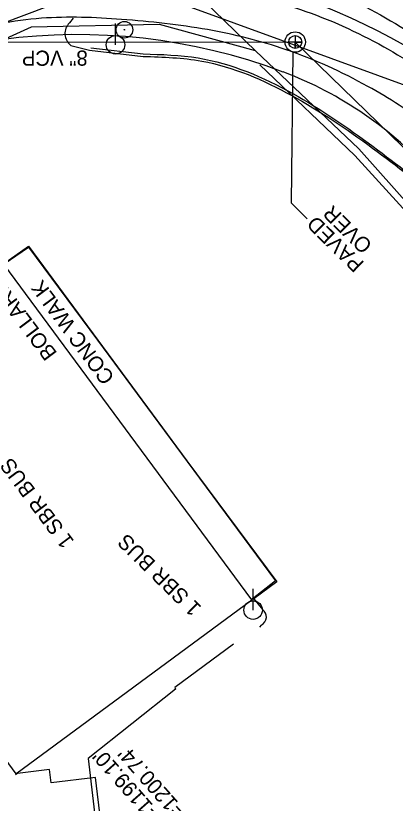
# Model space of a CAD drawing. Extents: x 1263837 to 1268319, y 770628 to 773628.
# Drawn here: x 1266313 to 1266413.1, y 772202.1 to 772410.1 of the extents above; entities that cross this region are included whole.
import ezdxf

# ---------------------------------------------------------------- set-up
doc = ezdxf.new("R2010")
doc.units = 0
for name, color, linetype in [('Exist Building', 7, 'Continuous'), ('Exist Building Text', 7, 'Continuous'), ('Exist Other Culture Located Object Text', 7, 'Continuous'), ('Exist Roads EOP Other', 7, 'Continuous'), ('Exist Roads EOP Other Text', 7, 'Continuous'), ('Exist Structure Minor Drop Inlet Top Elevation', 7, 'Continuous'), ('Exist Utilities Gas UG Line SUE LOS B', 7, 'Continuous'), ('Exist Utilities Gas UG Line SUE LOS C', 7, 'Continuous'), ('Exist Utilities Power Pole CELL', 7, 'Continuous'), ('Exist Utilities Water UG Line SUE LOS B', 7, 'Continuous'), ('Pattern 2', 7, 'Continuous'), ('Prop Conc 4in Sidewalk', 7, 'Continuous'), ('Prop Drainage Structure Junction Box Convert From Catch Basin Label', 7, 'Continuous'), ('Prop Horizontal Alignment', 7, 'Continuous'), ('Prop Retaining Wall', 7, 'Continuous'), ('Prop SS Fill Line', 7, 'Continuous'), ('Prop SS Fill Text', 7, 'Continuous'), ('Prop SS Transition Line', 7, 'Continuous'), ('Prop WCR CELL', 7, 'Continuous'), ('Scratch_Level_0', 7, 'Continuous'), ('Scratch_Level_2', 7, 'Continuous'), ('Scratch_Level_5', 7, 'Continuous')]:
    doc.layers.add(name, color=color, linetype=linetype)

# ---------------------------------------------------------------- blocks, each defined once
blk = doc.blocks.new('EXIST PROPERTY IRON PIN')
at = {"layer": 'Prop Conc 4in Sidewalk'}
for radius in [0.0441, 0.00141]:
    blk.add_circle((0, 0), radius, dxfattribs=at)
blk = doc.blocks.new('EXIST UTILITIES SANITARY SEWER MANHOLE')
at = {"layer": 'Prop WCR CELL'}
blk.add_lwpolyline([(0, 0.03425), (0, -0.03425), (0, 0), (0.03425, 0), (-0.03425, 0)], dxfattribs=at)
for radius in [0.05389, 0.03425]:
    blk.add_circle((0, 0), radius, dxfattribs=at)
blk = doc.blocks.new('EXIST UTILITIES POWER POLE')
at = {"layer": 'Exist Utilities Power Pole CELL'}
for q in [(0, 0.1125), (0, 0)]:
    blk.add_line((0, 0), q, dxfattribs=at)
blk.add_circle((0, 0), 0.049, dxfattribs=at)

msp = doc.modelspace()

# ---------------------------------------------------------------- linework, layer by layer
at = {"layer": 'Exist Building'}
for p, q in [((1266375.23, 772255.85), (1266309.82, 772344.48)), ((1266247.59, 772298.56), (1266312.99, 772209.92)), ((1266312.99, 772209.92), (1266375.23, 772255.85)), ((1266321.91, 772211.03), (1266313.4, 772209.99)), ((1266322.35, 772207.49), (1266321.91, 772211.03)), ((1266313.4, 772209.99), (1266312.91, 772209.63)), ((1266334.03, 772208.92), (1266322.35, 772207.49)), ((1266337.14, 772183.48), (1266334.03, 772208.92))]:
    msp.add_line(p, q, dxfattribs=at)
at = {"layer": 'Exist Roads EOP Other'}
msp.add_lwpolyline([(1266309.94, 772344.54), (1266316.31, 772348.99), (1266334.51, 772324.38), (1266358.19, 772292.37), (1266381.55, 772260.83), (1266375.33, 772256.01)], dxfattribs=at)
at = {"layer": 'Exist Utilities Gas UG Line SUE LOS B'}
for points in [[(1266634.89, 772116.41), (1266617.88, 772134.08), (1266593.74, 772162.87), (1266570.59, 772187.5), (1266552.2, 772208.93), (1266533.9, 772229.88), (1266520.79, 772243.67), (1266506.09, 772258.4), (1266476.3, 772293.88), (1266450.61, 772322.46), (1266432.17, 772342.72), (1266403.52, 772374.96), (1266376.24, 772400.79), (1266349.14, 772427.18), (1266329.27, 772447.31), (1266306.87, 772470.18), (1266286, 772492.58), (1266264.53, 772515.83), (1266241.63, 772542.64), (1266214.18, 772573.35), (1266190.07, 772598.41)], [(1266376.24, 772400.79), (1266350.86, 772407.74), (1266317.08, 772407.04), (1266271.2, 772386.3), (1266203.97, 772354.59), (1266162.66, 772329.58), (1266106.83, 772288), (1266086.58, 772274.45), (1266074.1, 772266.05)]]:
    msp.add_lwpolyline(points, dxfattribs=at)
at = {"layer": 'Exist Utilities Gas UG Line SUE LOS C'}
msp.add_lwpolyline([(1266457.07, 772059.93), (1266485, 772121.03), (1266506.31, 772156.87), (1266540.43, 772198.08), (1266541.09, 772218.23), (1266505.13, 772257.1), (1266475.32, 772292.21), (1266449.64, 772321.32), (1266402.45, 772373.22), (1266377.36, 772397.1)], dxfattribs=at)
at = {"layer": 'Exist Utilities Water UG Line SUE LOS B'}
msp.add_lwpolyline([(1266813.73, 772072.54), (1266793.78, 772088.05), (1266755.27, 772103.69), (1266718.33, 772109.44), (1266678.54, 772111.01), (1266653.19, 772143.96), (1266605.92, 772197.31), (1266538.03, 772271.69), (1266479.88, 772335.62), (1266421.78, 772389.51), (1266357.3, 772412.97), (1266321.15, 772412.43), (1266255.77, 772387.79), (1266212.97, 772357.83), (1266212.08, 772352.35), (1266208.85, 772350.26), (1266194.96, 772350.29), (1266178.01, 772373.6), (1266155.19, 772357.9), (1266088.3, 772309.2), (1266057.71, 772286.98)], dxfattribs=at)
at = {"layer": 'Pattern 2'}
msp.add_lwpolyline([(1266386.06, 772400.45), (1266385.61, 772360.68), (1266389.89, 772356.47)], dxfattribs=at)
at = {"layer": 'Prop Horizontal Alignment'}
for centre, radius, start, end in [((1275094.23, 780056.99), 11329.16, 216.983333, 223.309327), ((1266329.37, 772251.49), 153.62, 69.344, 125.8167), ((1266348.29, 772301.67), 100, 41.5645, 69.344)]:
    msp.add_arc(centre, radius, start, end, dxfattribs=at)
at = {"layer": 'Prop SS Fill Line'}
msp.add_line((1266332.8, 772401.59), (1266346.6, 772400.02), dxfattribs=at)
msp.add_spline([(1266346.6, 772400.02), (1266361.11, 772398.95), (1266386.07, 772389.55), (1266407.24, 772375.55), (1266426.22, 772361.02)], degree=3, dxfattribs=at)
at = {"layer": 'Prop SS Fill Text'}
for p, q in [((1266328.16, 772409.43), (1266327.13, 772408.22)), ((1266327.49, 772402.28), (1266332.41, 772401.03)), ((1266332.41, 772401.03), (1266346.62, 772399.36)), ((1266377.75, 772249.19), (1266377.27, 772248.65))]:
    msp.add_line(p, q, dxfattribs=at)
for points in [[(1266254.12, 772303.49), (1266281.48, 772323.69), (1266309.75, 772344.59), (1266316.36, 772349.23), (1266334.61, 772324.38), (1266358.15, 772292.51), (1266381.86, 772260.61), (1266375.76, 772256.12), (1266378.08, 772253.27)], [(1266370.44, 772244.15), (1266354.94, 772232.67), (1266355.16, 772232.29), (1266332.08, 772213.92), (1266335.21, 772186.92), (1266335.63, 772185.32)]]:
    msp.add_lwpolyline(points, dxfattribs=at)
for centre, major_axis, ratio, start_param, end_param in [((1266329.94, 772405.41), (-3.66, -1.57), 0.998613, 5.094295, 6.784605), ((1266376.71, 772251.31), (2.16, 1.05), 0.986481, 4.717764, 6.796398)]:
    msp.add_ellipse(centre, major_axis=major_axis, ratio=ratio, start_param=start_param, end_param=end_param, dxfattribs=at)
for points in [[(1266276.62, 772427.29), (1266296.76, 772434.14), (1266312.57, 772438.66), (1266334.71, 772440.84), (1266354.99, 772439.59), (1266376.7, 772435.9), (1266400.18, 772427.65), (1266423.73, 772414.83), (1266442.53, 772401.44), (1266462.31, 772384.69), (1266479.28, 772369.15)], [(1266436.57, 772368.38), (1266422.02, 772380.89), (1266405.87, 772391.44), (1266384.31, 772401.13), (1266363.54, 772406.42), (1266340.89, 772409.14), (1266319.77, 772409.42), (1266297.73, 772405.41), (1266278.46, 772399.08), (1266257.89, 772390.36), (1266236.47, 772379.38), (1266215.62, 772367.2), (1266196.71, 772355.5)], [(1266346.62, 772399.36), (1266362.06, 772398.12), (1266385.83, 772389.01), (1266407.13, 772375.16), (1266425.93, 772360.59)]]:
    msp.add_spline(points, degree=3, dxfattribs=at)
at = {"layer": 'Prop SS Transition Line'}
for points in [[(1266344.34, 772428.92), (1266367.71, 772426.04), (1266391.52, 772418.84), (1266413.16, 772408.02), (1266432.74, 772394.53), (1266452.23, 772378.67), (1266472.87, 772359.23)], [(1266339.45, 772427.21), (1266366.25, 772418.02), (1266388.1, 772411.74), (1266410.05, 772401.92), (1266429.01, 772389.72), (1266448.51, 772374.07), (1266467.93, 772354.23)]]:
    msp.add_spline(points, degree=3, dxfattribs=at)
at = {"layer": 'Scratch_Level_2'}
for centre, radius, start, end in [((1275094.23, 780056.99), 11459.16, 216.983333, 225.433333), ((1266329.37, 772251.49), 173.62, 43.2333, 125.8167)]:
    msp.add_arc(centre, radius, start, end, dxfattribs=at)
at = {"layer": 'Scratch_Level_5'}
for p, q in [((1266386.71, 772403.16), (1266276.72, 772402.93)), ((1266683.36, 772113.38), (1266386.71, 772403.16))]:
    msp.add_line(p, q, dxfattribs=at)

# ---------------------------------------------------------------- block references
at = {"layer": 'Exist Utilities Power Pole CELL', "xscale": 50, "yscale": 50}
for p in [(1266339.3, 772402.43), (1266375.6, 772253.13)]:
    msp.add_blockref('EXIST UTILITIES POWER POLE', p, dxfattribs=at)
at = {"layer": 'Prop Conc 4in Sidewalk', "xscale": 50, "yscale": 50}
msp.add_blockref('EXIST PROPERTY IRON PIN', (1266341.64, 772406.39), dxfattribs=at)
at = {"layer": 'Prop WCR CELL', "xscale": 50, "yscale": 50}
msp.add_blockref('EXIST UTILITIES SANITARY SEWER MANHOLE', (1266386.71, 772403.16), dxfattribs=at)

# ---------------------------------------------------------------- texts
at = {"layer": 'Exist Building Text'}
for rotation, p in [(126.9057, (1266328.52, 772271.34)), (135.4239, (1266362.19, 772253.95))]:
    msp.add_text('1 SBR BUS', height=4, rotation=rotation, dxfattribs=at).set_placement(p)
at = {"layer": 'Exist Other Culture Located Object Text'}
msp.add_text('BOLLARD', height=4, rotation=126.9057, dxfattribs=at).set_placement((1266324.04, 772321))
at = {"layer": 'Exist Roads EOP Other Text'}
msp.add_text('CONC WALK', height=4, rotation=126.4975, dxfattribs=at).set_placement((1266339.22, 772314.59))
at = {"layer": 'Exist Structure Minor Drop Inlet Top Elevation'}
msp.add_text("TOP=1200.74'", height=4, rotation=131.3556, dxfattribs=at).set_placement((1266365.37, 772191.71))
at = {"layer": 'Prop Drainage Structure Junction Box Convert From Catch Basin Label'}
msp.add_text("INV=1199.10'", height=4, rotation=131.3556, dxfattribs=at).set_placement((1266357.34, 772192.58))
at = {"layer": 'Prop Retaining Wall'}
for s, p in [('OVER', (1266407.3, 772349.73)), ('PAVED ', (1266405.14, 772344.84))]:
    msp.add_text(s, height=4, rotation=135.4418, dxfattribs=at).set_placement(p)
at = {"layer": 'Scratch_Level_0'}
msp.add_text('8" VCP', height=4, rotation=180.1229, dxfattribs=at).set_placement((1266331.95, 772400.91))

doc.saveas('drawing.dxf')
